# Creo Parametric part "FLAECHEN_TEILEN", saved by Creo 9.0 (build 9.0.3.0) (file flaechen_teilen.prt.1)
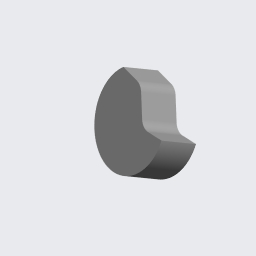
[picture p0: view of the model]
Materials in the file: S235JRG2

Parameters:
  BENENNUNG = "XXX"
  DATUM = "XX.XX.XX"
  ERSTELLER = "ARINDA"
  TEILETYP = "Fertigungsteil"
  PTC_MASTER_MATERIAL = "S235JRG2"
  SELECT_EN_NAME = "S235JRG2"
  SELECT_DIN_NAME = "RSt37-2"
  SELECT_DIN_NUMBER = "1.0038"
  SELECT_ASTM_NAME = "A 283 M Grade 2"
  MATERIAL_GROUP = "ME_ST_Baustahl"
  STANDARD_EN_DELIVERYSPEC = "DIN EN 10025"
  STANDARD_DIN_DELIVERYSPEC = "DIN 17100"

Other parameters: MASSE

Created from: ARINDA-STARTTEIL.PRT

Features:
  1. coordinate system "CS0"
  2. datum plane "DTM1", "T_RECHTS_Y-Z"
  3. datum plane "DTM2", "T_OBEN_X-Z"
  4. datum plane "DTM3", "T_VORNE_X-Y"
  5. datum axis "T_X-ACHSE"
  6. datum axis "A_1"
  7. datum axis "A_2"
  8. extrusion "Profil 1"
  9. extruded cut "Profil 2"
  10. round "Rundung 1"

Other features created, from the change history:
  feature "Kopieren 1"
  feature "Flächenbereich Trennen 1"
  feature "Fläche Teilen 1"
  feature "Versatz 1"
  feature "Versatz 2"
  revolve "Drehen 1"

Other named items: T_BASIC, T_Y-ACHSE, T_Z-ACHSE

Layers: 00_STD-ACHSEN, 00_STD-EBENEN, 00_STD-KOORDSYS, 01_ACHSEN, FLAECHEN, SAMMELFLÄCHEN, VOLUMENGEOMETRIE

Surfaces: 5 plane, 2 cylinder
